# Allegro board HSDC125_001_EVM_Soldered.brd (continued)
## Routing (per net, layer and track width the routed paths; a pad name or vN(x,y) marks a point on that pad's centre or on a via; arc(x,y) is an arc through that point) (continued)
N16916452: length 7.2
  TOP w0.203: JP1.1 22.68,62.6 23.32,63.24 R122.1 23.34,63.72 23.11,63.95 U7.11
N16916458: length 13.7
  TOP w0.203: U8.6 18.3,54.53 18.31,54.53 R100.2 19.84,54.53 21.44,56.13 JP1.2 24.51,57.96 24.51,60.68 23.34,61.85 R122.2
N16916991: length 17.8
  TOP w0.203: U8.5 15.77,53.26 15.57,53.47 15.57,59.21 17.3,60.93 18.34,60.93 20.64,63.24 R99.2 22.05,63.72 22.31,63.99 U7.10
N16919313: length 2
  TOP w0.203: U7.5 v1(18.93,69.27)
  BOTTOM w0.203: R94.1 19.42,69.27 v1(18.93,69.27)
N16919318: length 4.1
  TOP w0.127: R96.1 18.33,68.57 18.68,68.22 18.86,68.22 v1(19.11,68.47) U7.6
  TOP w0.203: C45.1 18.1,69.2 18.33,68.97 R96.1
  BOTTOM w0.127: v1(19.11,68.47) 19.52,68.47 R94.2
N16919400: length 3.5
  TOP w0.127: R95.1 18.33,67.58 18.68,67.93 18.95,67.93 19.21,67.67 U7.7
  TOP w0.203: C49.2 17.98,66.81 18.33,67.17 R95.1
N16919998: length 3
  TOP w0.203: R101.1 20.12,74.01 20.11,74.01 U7.1
N16965307: length 4.6
  TOP w0.203: U4.7 46.35,69.91 46.4,69.86 R120.1 46.4,68.73 46.42,68.7 R83.1
N16965335: length 2.6
  TOP w0.203: C34.1 48.33,72.71 48.39,72.77 48.39,73.06 48.03,73.42 U4.9
N16968702: length 2.4
  TOP w0.203: R98.2 29.99,72.47 U7.24 U7.23
N16982334: length 1.8
  TOP w0.203: U8.7 18.08,55.8 18.16,55.88 R121.1
N17024118: length 13.6
  TOP w0.127: R95.2 17.43,67.56 17.06,67.93 16.65,67.93 15.6,68.98 15.6,73.01 16.1,73.52 16.1,74.83 15.6,75.34 15.6,76.76 16.01,77.17 U16.5 16.01,79.28 J13.2
N17024121: length 13.3
  TOP w0.127: R96.2 17.43,68.58 17.06,68.21 16.76,68.21 15.88,69.1 15.88,72.9 16.38,73.41 16.38,75.06 17.01,75.68 U16.3 17.01,76.71 16.48,77.24 16.48,78.07 16.64,78.23 J13.3
N17075681: length 6.6
  TOP w0.203: v1(41.68,43.31) U1.11 42.65,43.31
  BOTTOM w0.203: R131.1 41.66,43.29 v1(41.68,43.31)
N17076650: length 1.6
  TOP w0.203: J18.1 40.65,52.8 40.64,52.79 C61.1
N17077181: length 2.1
  BOTTOM w0.203: R132.1 JMP4.2
N17077214: length 2.1
  BOTTOM w0.203: R27.1 JMP4.3
N17077452: length 2.1
  BOTTOM w0.203: R133.1 JMP5.2
N17077486: length 2.1
  BOTTOM w0.203: R134.1 JMP5.3
N17077740: length 2.1
  BOTTOM w0.203: R135.1 JMP6.2
N17077774: length 2
  BOTTOM w0.203: R136.1 JMP6.3
N17078062: length 2.1
  BOTTOM w0.203: R137.1 JMP7.2
N17078096: length 2.1
  BOTTOM w0.203: R138.1 JMP7.3
N17078348: length 2.1
  BOTTOM w0.203: R139.1 JMP8.2
N17078382: length 2.1
  BOTTOM w0.203: R140.1 JMP8.3
N17078649: length 2.1
  BOTTOM w0.203: R141.1 JMP9.2
N17078683: length 2.1
  BOTTOM w0.203: R142.1 JMP9.3
N17082573: length 2.3
  BOTTOM w0.203: J25.1 30.23,29.64 30.21,29.62 R150.1
N17083396: length 2.1
  BOTTOM w0.203: R152.1 J27.1
N17083699: length 2.1
  BOTTOM w0.203: R154.1 JMP13.2
N17083743: length 2.1
  BOTTOM w0.203: R155.1 JMP13.3
N17098810: length 1.8
  TOP w0.203: D1.1 35.02,78.85 35.05,78.82 R82.1
N17100064: length 3.3
  BOTTOM w0.203: U23.2 47.92,32.16 47.95,32.19 R168.2
N17100067: length 2.1
  BOTTOM w0.203: U23.3 48.16,31.51 48.44,31.24 R169.2
N17100133: length 2.2
  BOTTOM w0.203: J31.3 50.49,15.51 50.5,15.51 R170.2
N17100137: length 17.6
  TOP w0.203: v1(42.57,23.14) 42.57,20.51 45.02,18.05 J31.2
  BOTTOM w0.203: U23.5 v1(42.57,23.14)
N17100618: length 4.8
  TOP w0.127: R171.1 69.17,40.71 L7.4 68.02,40.71 67.76,40.45 64.98,40.45 R183.2
N17100645: length 4.8
  TOP w0.127: R172.1 69.17,39.91 L7.1 68.02,39.91 67.76,40.17 64.98,40.17 R184.2
N17100678: length 4.8
  TOP w0.127: R173.1 69.17,43.25 L3.4 68.02,43.25 67.76,42.99 64.98,42.99 R185.2
N17100691: length 4.8
  TOP w0.127: R186.2 64.98,42.71 67.76,42.71 68.02,42.45 L3.1 69.17,42.45 R174.1
N17100724: length 4.8
  TOP w0.127: R187.2 64.98,45.53 67.76,45.53 68.02,45.79 L4.4 69.17,45.79 R175.1
N17100737: length 4.8
  TOP w0.127: R188.2 64.98,45.25 67.76,45.25 68.02,44.99 L4.1 69.17,44.99 R176.1
N17100772: length 4.8
  TOP w0.127: R177.1 69.17,38.17 L5.4 68.02,38.17 67.76,37.91 64.98,37.91 R189.2
N17100781: length 4.8
  TOP w0.127: R178.1 69.17,37.37 L5.1 68.02,37.37 67.76,37.63 64.98,37.63 R190.2
N17106321: length 1.6
  TOP w0.203: J30.1 49.79,52.8 49.78,52.79 C64.1
N17106522: length 2.3
  BOTTOM w0.203: R182.1 33.18,27.11 33.17,27.1 J25.2
N17107170: length 2.6
  TOP w0.203: R5.2 15.83,33.7 15.86,33.73 R12.2 15.43,34.87 Q1.1
N17107194: length 4.2
  TOP w0.203: Q2.1 13.34,36.67 13.34,36.67 R11.1 15.5,36.67 16.38,37.55 Q1.3
N17107221: length 4.7
  TOP w0.203: Q2.3 10.53,37.62 9.07,39.08 R13.1
N17117344: length 2.4
  BOTTOM w0.203: J33.1 40.71,19.94 40.72,19.93 R194.1
N17130852: length 2.2
  BOTTOM w0.203: R180.1 JMP16.2
N17130854: length 2.2
  BOTTOM w0.203: R204.1 JMP15.2

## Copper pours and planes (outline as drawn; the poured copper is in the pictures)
GND on TOP: 45.72,73.03 45.72,71.12 45.47,70.87 44.83,70.87 44.83,70.36 45.59,70.36 45.97,70.74 45.97,73.03
GND on TOP: 71.48,63.37 75.72,63.37 76.5,62.59 76.5,62.15 86.26,62.15 86.28,62.18 86.28,65.07 85.8,65.56 71.73,65.56 71.45,65.28 71.45,63.4
GND on TOP: 46.74,73.03 46.74,71.63 47.12,71.25 47.62,71.25 47.62,72.39 46.99,73.03
GND on TOP: 45.21,75.31 45.97,75.31 45.97,76.33 46.2,76.56 46.61,76.56 46.66,76.61 48.31,76.61 48.67,76.25 50.7,76.25 52.81,78.36 64.01,78.36 65.23,77.14 65.23,72.26 66.75,70.74 68.91,70.74 71.93,73.76 75.74,73.76 76.71,74.73 76.71,81.13 75.49,82.35 47.62,82.35 45.47,80.19 45.47,76.33 45.21,76.07
GND on TOP: 55.17,63.09 50.62,63.09 49.86,63.86 49.86,66.07 50.5,66.7 54.61,66.7 55.24,66.07 55.24,63.17
GND on TOP, BOTTOM: 20.27,83.13 20.27,78.54 24.1,78.54 24.1,83.13
GND on TOP, BOTTOM: 9.3,78.44 9.3,83.11 13.18,83.11 13.18,82.17 13.36,81.57 13.84,81.17 13.84,78.44
GND on L2, L5: 15.35,83.19 17.93,83.19 17.93,82.17 18.25,81.4 19.78,81.4 20.1,82.17 20.1,83.19 88.27,83.19 88.27,0.64 0.64,0.64 0.64,83.19 13.18,83.19 13.18,82.17 13.5,81.4 15.03,81.4 15.35,82.17
VCC_3P3V on TOP: 35.71,79.3 35.71,80.9 36.42,81.61 41.22,81.61 41.88,80.95 41.88,77.85 41.86,77.83 37.31,77.83 36.83,78.31 36.83,78.94 36.45,79.32 35.74,79.32
VCC_3P3V on L4: 15.35,83.19 17.93,83.19 17.93,82.17 18.25,81.4 19.78,81.4 20.1,82.17 20.1,83.19 88.27,83.19 88.27,0.64 0.64,0.64 0.64,83.19 13.18,83.19 13.18,82.17 13.5,81.4 15.03,81.4 15.35,82.17
BOARD_3P3V on TOP: 44.83,76.33 44.58,76.07 40.77,76.07 40.77,76.96 40.89,77.09 42.29,77.09 42.29,78.36 44.2,78.36 44.83,77.72
BOARD_3P3V on L3: 15.35,83.19 17.93,83.19 17.93,82.17 18.25,81.4 19.78,81.4 20.1,82.17 20.1,83.19 88.27,83.19 88.27,53.2 72.07,53.2 72.07,60.97 37.01,60.97 37.01,53.19 0.64,53.19 0.64,83.19 13.18,83.19 13.18,82.17 13.5,81.4 15.03,81.4 15.35,82.17
BOARD_5V on L4: 17.79,38.53 88.14,38.53 88.14,26.59 87.96,26.42 76.58,26.42 70.74,32.26 14.5,32.26 13.36,33.4 13.36,37.21 12.65,37.92 6.12,37.92 4.76,39.28 4.76,40.01 5.12,40.36 15.96,40.36
BOARD_IN on TOP: 47.24,74.3 50.29,74.3 52.65,71.93 52.65,68.61 62.84,68.61 62.84,72.19 54.99,72.19 51.69,75.49 48.56,75.49 48.18,75.87 46.74,75.87 46.74,75.29 47.12,75.29 47.24,75.16
PWRIN_SW on TOP: 75.87,72.34 71.83,72.34 66.73,67.23 59.54,67.23 59.49,67.18 59.49,64.36 67.72,64.36 70.74,67.39 75.9,67.39 75.9,72.31
USB_5V on BOTTOM: 16.05,78.49 15.39,78.49 14.15,77.24 14.15,75.31 14.45,75.01 57.2,75.01 58.95,73.25 62.46,73.25 63.55,74.35 63.55,76.71 62.1,78.16 58.39,78.16 57.02,76.78 17.14,76.78 16.66,77.27 16.66,78.03 16.71,78.08 16.71,78.11 16.31,78.51 16.08,78.51
VIO on L3: 70.87,0.64 0.81,0.64 0.81,52.03 37.78,52.03 37.82,52.07 37.82,59.63 37.9,59.7 71.25,59.7 71.25,52.3 88.26,52.3 88.26,0.64 70.92,0.64
N16965311 on TOP: 44.96,73.79 41.4,73.79 40.77,74.42 40.77,75.31 43.69,75.31 43.94,75.06 44.96,75.06

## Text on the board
BOTTOM: LAYER 4 - BOTTOM SIDE
Ref Des/Assembly Bottom: ASSEMBLY- BOTTOM SIDE
Board Geometry/Soldermask Bottom: SOLDERMASK BOTTOM
Package Geometry/Pastemask Bottom: PASTEMASK BOTTOM
Ref Des/Silkscreen Bottom: SILKSCREEN BOTTOM
TOP: LAYER 1 - TOP SIDE
Ref Des/Assembly Top: ASSEMBLY- TOP SIDE
Board Geometry/Soldermask Top: SOLDERMASK TOP
Package Geometry/Pastemask Top: PASTEMASK TOP
Ref Des/Silkscreen Top: SDA_CFG1 | SCL_CFG0 | SDA_CTL | SCL_CTL | AAR_SDA | AAR_SCL | GND | USB | AC_EN | 3P3V | VIO | SCL_SNK | SDA_SNK | VCC | DCGAIN | PD | VCC_3P3V | SCL_SRC | MODE | LV | TEST1 | PU | SDA_SRC | HPDOUT_SEL | TXPRE | SIGDET | OUT | EQ1 | EQ0/ADDR | USB 5V | WALL | OFF | CTLEMAP_SEL | TXSWG | HPD_SNK | LINEAR_EN | BOARD | RESET | BOARD_5V | SILKSCREEN TOP | HSDC125 | LABEL
L2: LAYER 2 - GND PLANE
L3: LAYER 3 - PWR PLANE
L4: LAYER 4 - L4
L5: LAYER 5 - L5
XSECTION_CHART: *  SURFACE - AIR 0 MIL | *  DIELECTRIC - AIR 0.8 MIL | L1 TOP CONDUCTOR - COPPER 1.2 MIL | *  DIELECTRIC - FR-4 5 MIL | L2 L2 PLANE - COPPER 1.2 MIL | *  DIELECTRIC - FR-4 20 MIL | L3 L3 PLANE - COPPER 1.2 MIL | L4 L4 PLANE - COPPER 1.2 MIL | L5 L5 PLANE - COPPER 1.2 MIL | L6 BOTTOM CONDUCTOR - COPPER 1.2 MIL | DESIGN CROSS SECTION CHART | ___________________________ | TOTAL THICKNESS 63.8 MIL | 1-6
DIMENSION: FABRICATION DRAWING | CAD ORIGIN
User.6: LAYER 1 | LAYER 2 | LAYER 3 | LAYER 4 | LAYER 5 | LAYER 6 | LAYER | NO. | TABLE 1: | TOP | L2_GND | L3_PWR | L4_PWR | L5_GND | BOTTOM | NAME | DIFFIRENTIAL PAIR | IMPEDANCE (OHMS) | 100 +/- 10% | DIFF TRACE | WIDTH | 0.005" | SPACING | 0.006" | SINGLE ENDED | 50 +/- 10% | TRACE WIDTH | 0.008" | REFERENCE | SPECIAL FAB NOTES: | PLACE DRILL CHART HERE: | MIN. ANNULAR RING 2 MIL EXTERNAL PER IPC-6012C | REGISTRATION TOLERANCES: METAL +/- X MIL,HOLES +/- X MIL | IMPEDANCE CONTROL: | BOARD SIZE (REFER ALSO ARRAY/PANEL PROFILING INFORMATION) | MIXED DIELECTRIC: | LAMINATE MATERIAL: | THICKNESS: | TOLERANCE: | COPPER THICKNESS (FINISHED): | BOARD FINISH: | NUMBER OF LAYERS: | MIN. TRACK WIDTH: | MIN. CLEARANCE  : | MIN. VIA PAD/DRILL: | THIEVING ALLOWED: | X | OUTER: | INNER SIGNAL: | INNER PLANE: | OTHER: | SILKSCREEN: | SOLDERMASK: (PER IPC-6011,6012) | BOARD SURFACE TREATMENT: | ADDITIONAL REQUIREMENTS: | VENDOR MARKING: | SILKSCREEN COLOR: | SOLDERMASK COLOR: | THROUGH-HOLE VIA TREATMENT: | VIA FILL USING COPPER AND PLATED OVER SMOOTH | VIA FILL USING NON-CONDUCTIVE EPOXY AND PLATED OVER SMOOTH | FOR WIRE BONDING: | VENDOR DATE CODE,UL,LOGO: | FR-4 HIGH Tg | 0.062" +/-10% | IPC-6012C CLASS 2 | IPC-6012C CLASS 3 | MICRO-SECTION | CERTIFICATES OF COMPLIANCE | NICKEL/GOLD (ENIG) | IMMERSION TIN | HARD GOLD | IN AN OPEN AREA | 1/4 OZ. | OPEN | NO | 6 | 5.0 MIL | X.X MIL | 16/08 MIL | NONE | DESIGN INFORMATION | ROGERS 4350B | 0.093" +/-10% | YES | TDR REPORTS/COUPONS | WHITE | GREEN | SOFT GOLD | TENTED | 1/2 OZ. | BOW & TWIST: | ORGANIC (OSP) | OTHER | WHERE INDICATED (SEE DRAWING) | YES - SEE TABLE 1 | ETCH | IDENTIFIER: | BLUE | RoHS | 1.0 OZ. | SILKSCREEN | PER SUPPLIED ARTWORK | ALL x MIL VIAS | ALL LASER DRILLS | ALL MECH VIAS | ELECTRICAL TEST | UL 94V-0 | HASL | 2.0 OZ. | BREAK-AWAY | ENEPIG
User.10: FIGURE | FINISHED_SIZE | 8.0 | 15.75 | 40.16 | 62.99 | 70.87 | 118.11 | 137.8 | 33.46 | 35.04 | 66.93 | 125.0 | 41.34x25.59 | 51.18x27.56 | 66.93x35.43 | 106.3x35.43 | DRILL CHART: TOP to BOTTOM | ALL UNITS ARE IN MILS | TOLERANCE_DRILL | +3.0/-3.0 | +3.15/-3.15 | +3.15/-1.97 | +1.97/-1.97 | +3.94/-3.94 | +2.0/-2.0 | PLATED | NON-PLATED | QTY | 274 | 16 | 80 | 3 | 2 | 1 | 4 | 415 | TOTAL HOLES:
